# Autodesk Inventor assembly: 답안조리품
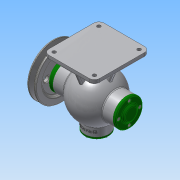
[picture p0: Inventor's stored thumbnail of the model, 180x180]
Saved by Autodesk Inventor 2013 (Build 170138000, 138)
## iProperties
Created: 2018-06
Part Number: 답안조리품
Document SubType Name: Assembly
Designer: Administrator
Author: Administrator
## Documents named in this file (19)
- C:\Users\Administrator\Desktop\480612V1002\답안조리품.iam
- C:\Users\Administrator\Desktop\480612V1002\본체.ipt
- C:\Users\Administrator\Desktop\480612V1002\V-벨트풀리.ipt
- C:\Users\Administrator\Desktop\480612V1002\너트 M8.ipt
- C:\Users\Administrator\Desktop\480612V1002\뒤커버.ipt
- C:\Users\Administrator\Desktop\480612V1002\멈춤링 15x1.ipt
- C:\Users\Administrator\Desktop\480612V1002\멈춤링 35x1.6.ipt
- 멈춤링 35x1.6.ipt
- C:\Users\Administrator\Desktop\480612V1002\베어링 6202.ipt
- 베어링 6202.ipt
- C:\Users\Administrator\Desktop\480612V1002\볼트 M4x12.ipt
- C:\Users\Administrator\Desktop\480612V1002\볼트 M4x16.ipt
- C:\Users\Administrator\Desktop\480612V1002\부시.ipt
- C:\Users\Administrator\Desktop\480612V1002\상부커버.ipt
- C:\Users\Administrator\Desktop\480612V1002\슬라이드.ipt
- C:\Users\Administrator\Desktop\480612V1002\앞커버.ipt
- C:\Users\Administrator\Desktop\480612V1002\오일 실 15 30 7.ipt
- C:\Users\Administrator\Desktop\480612V1002\키 4x4x12.ipt
- C:\Users\Administrator\Desktop\480612V1002\편심축.ipt
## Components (1 placed, 1 different names)
1. V-벨트풀리:1
